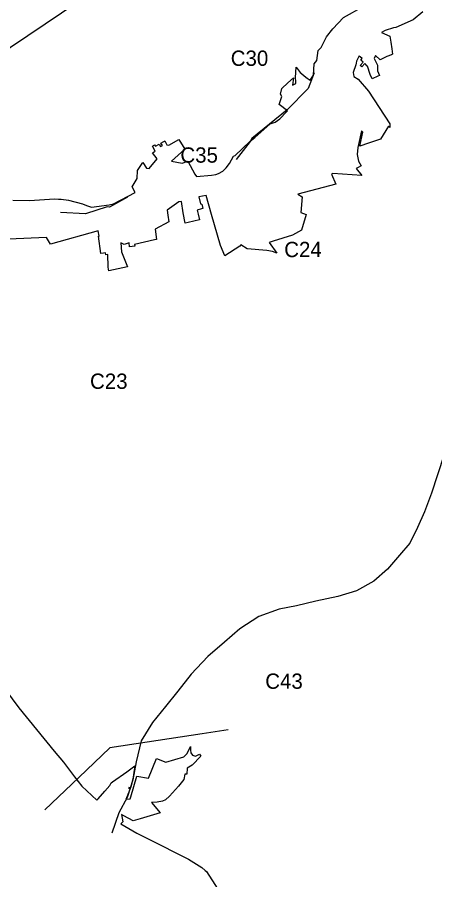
# Model space of a CAD drawing. Extents: x -557103 to -548162, y -1041918 to -1033974.
# Drawn here: x -554362 to -553543, y -1039045 to -1037353 of the extents above; entities that cross this region are included whole.
import ezdxf

# ---------------------------------------------------------------- set-up
doc = ezdxf.new("R2010")
doc.units = 0
for name, color, linetype in [('body3', 7, 'Continuous'), ('Vrstva 15', 7, 'Continuous'), ('Vrstva 16', 7, 'Continuous'), ('Vrstva 37', 7, 'Continuous')]:
    doc.layers.add(name, color=color, linetype=linetype)

msp = doc.modelspace()

# ---------------------------------------------------------------- linework, layer by layer
at = {"layer": 'body3'}
for p, q in [((-553721.7, -1037354.2), (-553682.3, -1037331.5)), ((-553566.5, -1037342.5), (-553585.3, -1037358.6)), ((-553742.9, -1037375.9), (-553721.7, -1037354.2)), ((-553585.3, -1037358.6), (-553619.5, -1037373.4)), ((-553755.1, -1037392), (-553742.9, -1037375.9)), ((-553640.1, -1037379.4), (-553647.4, -1037383.3)), ((-553623.9, -1037374.4), (-553640.1, -1037379.4)), ((-553619.5, -1037373.4), (-553623.9, -1037374.4)), ((-553765.8, -1037412.9), (-553755.1, -1037392)), ((-553647.4, -1037383.3), (-553631.4, -1037390.4)), ((-553631.4, -1037390.4), (-553629.3, -1037402.6)), ((-553771.6, -1037418.9), (-553765.8, -1037412.9)), ((-553629.3, -1037402.6), (-553627, -1037415.6)), ((-553774.5, -1037438.2), (-553771.6, -1037418.9)), ((-553691.1, -1037429.1), (-553693.5, -1037432.9)), ((-553689.1, -1037430.8), (-553691.1, -1037429.1)), ((-553685.2, -1037434.1), (-553689.1, -1037430.8)), ((-553659.4, -1037428.2), (-553661.7, -1037434.6)), ((-553650.3, -1037437.3), (-553659.4, -1037428.2)), ((-553636.9, -1037430.3), (-553650.3, -1037437.3)), ((-553628.1, -1037426.9), (-553636.9, -1037430.3)), ((-553626, -1037426.1), (-553628.1, -1037426.9)), ((-553627, -1037415.6), (-553626, -1037426.1)), ((-553781, -1037467.2), (-553779.8, -1037444.8)), ((-553779.8, -1037444.8), (-553774.5, -1037438.2)), ((-553697.8, -1037446.5), (-553698.9, -1037450.6)), ((-553697.1, -1037443.3), (-553697.8, -1037446.5)), ((-553696.2, -1037439.8), (-553697.1, -1037443.3)), ((-553695.1, -1037436.8), (-553696.2, -1037439.8)), ((-553693.5, -1037432.9), (-553695.1, -1037436.8)), ((-553689.3, -1037448.1), (-553683.4, -1037441.5)), ((-553686.3, -1037450.7), (-553689.3, -1037448.1)), ((-553688.1, -1037437.5), (-553685.2, -1037434.1)), ((-553683.4, -1037441.5), (-553688.1, -1037437.5)), ((-553680.4, -1037444.2), (-553686.3, -1037450.7)), ((-553678.4, -1037445.9), (-553680.4, -1037444.2)), ((-553676, -1037448.6), (-553678.4, -1037445.9)), ((-553675.1, -1037449.5), (-553676, -1037448.6)), ((-553661.7, -1037434.6), (-553655.3, -1037447.6)), ((-553655.3, -1037447.6), (-553655.3, -1037458.4)), ((-553816.2, -1037471.6), (-553814.6, -1037451.3)), ((-553814.6, -1037451.3), (-553806.8, -1037461.6)), ((-553806.8, -1037461.6), (-553804.5, -1037463.7)), ((-553804.5, -1037463.7), (-553799.1, -1037468.3)), ((-553701.4, -1037457.7), (-553702.9, -1037462)), ((-553702.9, -1037462), (-553701.9, -1037469.7)), ((-553698.9, -1037450.6), (-553701.4, -1037457.7)), ((-553669.8, -1037465.5), (-553675.1, -1037449.5)), ((-553665.6, -1037474.5), (-553669.8, -1037465.5)), ((-553655.3, -1037458.4), (-553651.1, -1037467.5)), ((-553842.7, -1037493.2), (-553830.9, -1037482)), ((-553830.9, -1037482), (-553820, -1037472.2)), ((-553820, -1037472.2), (-553821.9, -1037486.8)), ((-553815.7, -1037479.6), (-553816.2, -1037471.6)), ((-553815.6, -1037483.6), (-553815.7, -1037479.6)), ((-553799.1, -1037468.3), (-553793.2, -1037472.7)), ((-553793.2, -1037472.7), (-553787.3, -1037476.8)), ((-553787.3, -1037476.8), (-553781, -1037467.2)), ((-553701.9, -1037469.7), (-553693, -1037475.2)), ((-553693, -1037475.2), (-553673.2, -1037498.5)), ((-553654.6, -1037469.3), (-553665.6, -1037474.5)), ((-553651.1, -1037467.5), (-553654.6, -1037469.3)), ((-553845.8, -1037504.4), (-553842.7, -1037493.2)), ((-553821.9, -1037486.8), (-553815.6, -1037483.6)), ((-553673.2, -1037498.5), (-553630.8, -1037562.5)), ((-553848.1, -1037524.5), (-553842.8, -1037508.8)), ((-553842.8, -1037508.8), (-553845.8, -1037504.4)), ((-553831.7, -1037536.8), (-553848.1, -1037524.5)), ((-553846.7, -1037552.8), (-553834, -1037539.3)), ((-553834, -1037539.3), (-553831.7, -1037536.8)), ((-553896, -1037589.1), (-553866, -1037562.8)), ((-553866, -1037562.8), (-553855.8, -1037559.1)), ((-553855.8, -1037559.1), (-553846.7, -1037552.8)), ((-553633.5, -1037567), (-553649.4, -1037592.8)), ((-553631.4, -1037569.4), (-553633.5, -1037567)), ((-553630.8, -1037562.5), (-553631.4, -1037569.4)), ((-553686.6, -1037576.4), (-553693.8, -1037608.7)), ((-553689.8, -1037606.1), (-553684.3, -1037578.7)), ((-553684.3, -1037578.7), (-553686.6, -1037576.4)), ((-554080, -1037600.3), (-554074.4, -1037597.1)), ((-554077.2, -1037605.3), (-554080, -1037600.3)), ((-554074.4, -1037597.1), (-554072.2, -1037596.2)), ((-554072.2, -1037596.2), (-554068.1, -1037603.7)), ((-554064.6, -1037604.1), (-554044.7, -1037593)), ((-554044.7, -1037593), (-554033.4, -1037612.2)), ((-553934.4, -1037624.9), (-553905.6, -1037597.2)), ((-553905.6, -1037597.2), (-553896, -1037589.1)), ((-553672.9, -1037600.6), (-553689.8, -1037606.1)), ((-553649.4, -1037592.8), (-553672.9, -1037600.6)), ((-554096.7, -1037606.6), (-554092.3, -1037604)), ((-554095.2, -1037609.2), (-554096.7, -1037606.6)), ((-554096.5, -1037619.4), (-554093.2, -1037617.2)), ((-554091.3, -1037616), (-554095.2, -1037609.2)), ((-554093.2, -1037617.2), (-554091.3, -1037616)), ((-554092.3, -1037604), (-554090.7, -1037606.6)), ((-554090.7, -1037606.6), (-554083.3, -1037602.3)), ((-554083.3, -1037602.3), (-554080.5, -1037607.1)), ((-554080.5, -1037607.1), (-554077.2, -1037605.3)), ((-554068.1, -1037603.7), (-554064.6, -1037604.1)), ((-554033.4, -1037612.2), (-554059.1, -1037635.5)), ((-553693.8, -1037608.7), (-553694.9, -1037622.9)), ((-554102.9, -1037650.4), (-554087.5, -1037631.5)), ((-554087.5, -1037631.5), (-554096.5, -1037619.4)), ((-553945.6, -1037640.5), (-553938, -1037625.9)), ((-553938, -1037625.9), (-553934.4, -1037624.9)), ((-553694.9, -1037622.9), (-553692.4, -1037635.6)), ((-554126.1, -1037654.3), (-554115.7, -1037638.3)), ((-554115.7, -1037638.3), (-554108.5, -1037649.3)), ((-554108.5, -1037649.3), (-554102.9, -1037650.4)), ((-554059.1, -1037635.5), (-554038.1, -1037639.9)), ((-554038.1, -1037639.9), (-554027.2, -1037635.6)), ((-554027.2, -1037635.6), (-554013.3, -1037661)), ((-553958.8, -1037655.5), (-553951.8, -1037649)), ((-553951.8, -1037649), (-553945.6, -1037640.5)), ((-553694.6, -1037648.7), (-553697.1, -1037649.9)), ((-553697.1, -1037649.9), (-553686.1, -1037664.2)), ((-553687.6, -1037645), (-553694.6, -1037648.7)), ((-553692.4, -1037635.6), (-553687.6, -1037645)), ((-554126.7, -1037669.5), (-554126.1, -1037654.3)), ((-554013.3, -1037661), (-554010.5, -1037666.1)), ((-554010.5, -1037666.1), (-553980.7, -1037663.1)), ((-553980.7, -1037663.1), (-553972, -1037661.7)), ((-553972, -1037661.7), (-553967, -1037660)), ((-553967, -1037660), (-553958.8, -1037655.5)), ((-553742.8, -1037660.2), (-553745.6, -1037661.5)), ((-553745.6, -1037661.5), (-553736.7, -1037680.9)), ((-553686.1, -1037664.2), (-553742.8, -1037660.2)), ((-554136.7, -1037686.1), (-554126.7, -1037669.5)), ((-553736.7, -1037680.9), (-553811.8, -1037700.4)), ((-554172.8, -1037719.7), (-554130.7, -1037697.4)), ((-554130.7, -1037697.4), (-554136.7, -1037686.1)), ((-553811.8, -1037700.4), (-553803.2, -1037705.7)), ((-554370.2, -1037712), (-554337.8, -1037712.6)), ((-554337.8, -1037712.6), (-554288.8, -1037709.5)), ((-554288.8, -1037709.5), (-554280.7, -1037710.1)), ((-554280.7, -1037710.1), (-554275.4, -1037710.5)), ((-554275.4, -1037710.5), (-554261, -1037712)), ((-554261, -1037712), (-554234, -1037719.7)), ((-554234, -1037719.7), (-554225.9, -1037722.5)), ((-554044.8, -1037715.4), (-554067.8, -1037732)), ((-554039.9, -1037714.7), (-554044.8, -1037715.4)), ((-554036.6, -1037737.3), (-554039.9, -1037714.7)), ((-553991.3, -1037703), (-554005.8, -1037705.9)), ((-554005.8, -1037705.9), (-554002.5, -1037719.6)), ((-554002.5, -1037719.6), (-553999.6, -1037720.2)), ((-553981.1, -1037740.7), (-553991.3, -1037703)), ((-553803.2, -1037705.7), (-553805.8, -1037736.3)), ((-554225.9, -1037722.5), (-554216.3, -1037725.9)), ((-554216.3, -1037725.9), (-554181.8, -1037721.7)), ((-554181.8, -1037721.7), (-554172.8, -1037719.7)), ((-554067.8, -1037732), (-554066.7, -1037742)), ((-554000.7, -1037729.4), (-554009.1, -1037731.7)), ((-554009.1, -1037731.7), (-554007.2, -1037739.7)), ((-553997.7, -1037728.6), (-554000.7, -1037729.4)), ((-553999.6, -1037720.2), (-553997.7, -1037728.6)), ((-553805.8, -1037736.3), (-553795.2, -1037740.6)), ((-554066.7, -1037742), (-554064.7, -1037754.7)), ((-554032.7, -1037757.5), (-554036.6, -1037737.3)), ((-554004.6, -1037750.8), (-554026.8, -1037756.1)), ((-554007.2, -1037739.7), (-554004.6, -1037750.8)), ((-553963.1, -1037801.3), (-553981.1, -1037740.7)), ((-553795.2, -1037740.6), (-553804.5, -1037771.2)), ((-554064.7, -1037754.7), (-554091, -1037769.3)), ((-554091, -1037769.3), (-554088.8, -1037789.1)), ((-554026.8, -1037756.1), (-554032.7, -1037757.5)), ((-554304.4, -1037785.4), (-554378.9, -1037788.6)), ((-554296.3, -1037798.7), (-554304.4, -1037785.4)), ((-554203.1, -1037772.5), (-554296.3, -1037798.7)), ((-554201.1, -1037782.8), (-554203.1, -1037772.5)), ((-554202.7, -1037783), (-554201.1, -1037782.8)), ((-554197.9, -1037816.9), (-554202.7, -1037783)), ((-553821.8, -1037781.2), (-553859.6, -1037792.5)), ((-553804.5, -1037771.2), (-553821.8, -1037781.2)), ((-554151.8, -1037799.1), (-554158.9, -1037796.2)), ((-554158.9, -1037796.2), (-554157.1, -1037813.5)), ((-554142.5, -1037796.2), (-554151.8, -1037799.1)), ((-554141.7, -1037803.8), (-554142.5, -1037796.2)), ((-554131.3, -1037802.7), (-554141.7, -1037803.8)), ((-554092.4, -1037790.1), (-554131.6, -1037799.2)), ((-554131.6, -1037799.2), (-554131.3, -1037802.7)), ((-554088.8, -1037789.1), (-554092.4, -1037790.1)), ((-553954.4, -1037821.7), (-553963.1, -1037801.3)), ((-553925.4, -1037802.3), (-553954.4, -1037821.7)), ((-553923.1, -1037799.8), (-553925.4, -1037802.3)), ((-553910.6, -1037807.6), (-553923.1, -1037799.8)), ((-553859.6, -1037792.5), (-553867.8, -1037795.3)), ((-553867.8, -1037795.3), (-553852.8, -1037816.3)), ((-554192.3, -1037816.1), (-554197.9, -1037816.9)), ((-554188.4, -1037815.5), (-554192.3, -1037816.1)), ((-554187.8, -1037819.3), (-554188.4, -1037815.5)), ((-554183.8, -1037818.8), (-554187.8, -1037819.3)), ((-554183.6, -1037843.2), (-554183.8, -1037818.8)), ((-554157.1, -1037813.5), (-554148.3, -1037836.6)), ((-553872.1, -1037810.7), (-553910.6, -1037807.6)), ((-553861.3, -1037812.8), (-553872.1, -1037810.7)), ((-553852.8, -1037816.3), (-553861.3, -1037812.8)), ((-554148.3, -1037836.6), (-554145.8, -1037843.2)), ((-554182.8, -1037848.2), (-554183.6, -1037843.2)), ((-554182.3, -1037850.7), (-554182.8, -1037848.2)), ((-554145.8, -1037843.2), (-554182.3, -1037850.7)), ((-554419.3, -1038628.4), (-554358.8, -1038707.9)), ((-554358.8, -1038707.9), (-554289.2, -1038793)), ((-554028.4, -1038797.4), (-554022.2, -1038784.1)), ((-554022.2, -1038784.1), (-554021.8, -1038791.3)), ((-554289.2, -1038793), (-554271.3, -1038814.9)), ((-554035.1, -1038804.5), (-554028.4, -1038797.4)), ((-554021.8, -1038791.3), (-554021.4, -1038796.5)), ((-554021.4, -1038796.5), (-554018.1, -1038801.1)), ((-554018.1, -1038801.1), (-554012.3, -1038802.8)), ((-554012.3, -1038802.8), (-554004.3, -1038799.3)), ((-554004.3, -1038799.3), (-554001.6, -1038803.1)), ((-554271.3, -1038814.9), (-554249.4, -1038843.5)), ((-554104.1, -1038845.9), (-554088.7, -1038807.7)), ((-554088.7, -1038807.7), (-554070.4, -1038814.5)), ((-554070.4, -1038814.5), (-554035.1, -1038804.5)), ((-554001.6, -1038803.1), (-554018.9, -1038820.4)), ((-554174.7, -1038853.4), (-554147.1, -1038833.4)), ((-554147.1, -1038833.4), (-554131.3, -1038821.9)), ((-554131.3, -1038821.9), (-554135.2, -1038847.8)), ((-554028.8, -1038826.7), (-554029.5, -1038838.5)), ((-554018.9, -1038820.4), (-554028.8, -1038826.7)), ((-554249.4, -1038843.5), (-554235.2, -1038861.9)), ((-554139.1, -1038882.8), (-554127.4, -1038841.9)), ((-554135.2, -1038847.8), (-554139, -1038863)), ((-554127.4, -1038841.9), (-554104.1, -1038845.9)), ((-554034.8, -1038848.9), (-554045.2, -1038861.7)), ((-554033.4, -1038838.2), (-554034.8, -1038848.9)), ((-554029.5, -1038838.5), (-554033.4, -1038838.2)), ((-554235.2, -1038861.9), (-554205.5, -1038889.1)), ((-554190.2, -1038871.9), (-554179.9, -1038860.3)), ((-554179.9, -1038860.3), (-554177.4, -1038855.4)), ((-554177.4, -1038855.4), (-554174.7, -1038853.4)), ((-554139, -1038863), (-554142.2, -1038871.5)), ((-554045.2, -1038861.7), (-554063.3, -1038881.4)), ((-554205.5, -1038889.1), (-554203.1, -1038886.4)), ((-554203.1, -1038886.4), (-554190.2, -1038871.9)), ((-554147.4, -1038884.4), (-554148.9, -1038887.4)), ((-554148.9, -1038887.4), (-554140.2, -1038886.5)), ((-554145.7, -1038880.2), (-554147.4, -1038884.4)), ((-554144.2, -1038876.5), (-554145.7, -1038880.2)), ((-554143.2, -1038874.2), (-554144.2, -1038876.5)), ((-554142.2, -1038871.5), (-554143.2, -1038874.2)), ((-554140.2, -1038886.5), (-554139.1, -1038882.8)), ((-554063.3, -1038881.4), (-554070.9, -1038888.4)), ((-554087.1, -1038893.4), (-554098.2, -1038894)), ((-554098.2, -1038894), (-554081.4, -1038914.4)), ((-554077.2, -1038891.3), (-554087.1, -1038893.4)), ((-554070.9, -1038888.4), (-554077.2, -1038891.3)), ((-554152.5, -1038919.9), (-554157, -1038917.5)), ((-554157, -1038917.5), (-554155, -1038932)), ((-554134.5, -1038929.8), (-554152.5, -1038919.9)), ((-554081.4, -1038914.4), (-554120.8, -1038925.8)), ((-554155, -1038932), (-554158.6, -1038935.8)), ((-554158.6, -1038935.8), (-554127.1, -1038954.2)), ((-554120.8, -1038925.8), (-554134.5, -1038929.8)), ((-554127.1, -1038954.2), (-554104.7, -1038965.3)), ((-554104.7, -1038965.3), (-554025.7, -1039004.7)), ((-554025.7, -1039004.7), (-553999.7, -1039021.4)), ((-553999.7, -1039021.4), (-553993.2, -1039027.2)), ((-553993.2, -1039027.2), (-553990.6, -1039029.5)), ((-553990.6, -1039029.5), (-553957.8, -1039080.2))]:
    msp.add_line(p, q, dxfattribs=at)
at = {"layer": 'Vrstva 15'}
for p, q in [((-554071.2, -1038705.6), (-554096.7, -1038736.9)), ((-554142.1, -1038863.7), (-554143.8, -1038867.1))]:
    msp.add_line(p, q, dxfattribs=at)
for points in [[(-553779.2, -1037462.3), (-553791, -1037492.9), (-553832.3, -1037535.3), (-553901.6, -1037591.5), (-553905.3, -1037597.3), (-553932.2, -1037632.7)], [(-554145.4, -1037706.2), (-554181.1, -1037726.2), (-554185.7, -1037725.6), (-554227.9, -1037739), (-554276.9, -1037736.7)], [(-553525.2, -1038212.9), (-553549.1, -1038287.3), (-553563.1, -1038323.6), (-553577.1, -1038354.5), (-553592.1, -1038385.3), (-553612, -1038408.7), (-553636, -1038436.1), (-553662.8, -1038459.5), (-553696.2, -1038478.5), (-553733.4, -1038489.9), (-553775.9, -1038499.2), (-553814, -1038507.8), (-553848.3, -1038514.8), (-553888.1, -1038528.8), (-553925.2, -1038553), (-553955.6, -1038579.2)], [(-553955.6, -1038579.2), (-553988.1, -1038607.6), (-554020.5, -1038641.8), (-554047, -1038675.4), (-554071.2, -1038705.6)], [(-553948.2, -1038751.5), (-553999, -1038759), (-554106.9, -1038775.6), (-554179.9, -1038786.6), (-554240.9, -1038845.1), (-554307.8, -1038908.4)], [(-554096.7, -1038736.9), (-554118.9, -1038772.7), (-554128.7, -1038814.1), (-554134.8, -1038849.1)], [(-554134.8, -1038849.1), (-554146.2, -1038883.8), (-554162.3, -1038914.4), (-554176.3, -1038954)]]:
    msp.add_lwpolyline(points, dxfattribs=at)
at = {"layer": 'Vrstva 16'}
msp.add_lwpolyline([(-554172.9, -1037275.9), (-554409.6, -1037435.4), (-554469.3, -1037482.8), (-554516.7, -1037530.1), (-554559, -1037580), (-554569, -1037664.7), (-554661.2, -1037749.5), (-554907.8, -1037851.7), (-555066.3, -1037953.4), (-555188.4, -1037993.2), (-555425.1, -1038050.6)], dxfattribs=at)

# ---------------------------------------------------------------- texts
at = {"layer": 'Vrstva 37'}
for s, p in [('C30', (-553943.1, -1037448.8)), ('C35', (-554041.8, -1037638.7)), ('C24', (-553838.2, -1037824)), ('C23', (-554219, -1038082.4)), ('C43', (-553875.4, -1038670.8))]:
    msp.add_text(s, height=30, dxfattribs=at).set_placement(p)

doc.saveas('drawing.dxf')
